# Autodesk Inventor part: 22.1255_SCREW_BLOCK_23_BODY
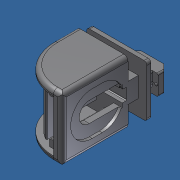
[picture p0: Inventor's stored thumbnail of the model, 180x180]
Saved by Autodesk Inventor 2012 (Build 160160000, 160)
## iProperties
Created: 2016-06
Part Number: 22.1255_SCREW_BLOCK_23_BODY
Material: ABS Plastic
Document SubType Name: Modeling
Designer: Admin
Density: 1.06 g/cm^3
Mass: 5.06959 g
Surface Area: 48.0858 cm^2
Volume: 4.78263 cm^3
Author: Admin
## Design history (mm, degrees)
feature "Base1"
body "Solid1"
